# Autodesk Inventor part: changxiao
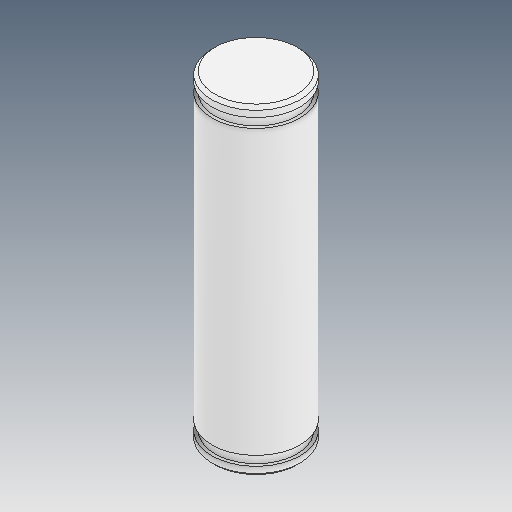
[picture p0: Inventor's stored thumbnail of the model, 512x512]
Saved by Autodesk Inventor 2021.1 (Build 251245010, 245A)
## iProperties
Created: 2021-05
Part Number: changxiao
Material: Ogólny
Document SubType Name: Modeling
Designer: user
Density: 1 g/cm^3
Appearance: Domyślna
Author: user
Revision Number: ÈÎºÎ
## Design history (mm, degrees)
feature "ÊäÈë1"
node "Bryła1"
